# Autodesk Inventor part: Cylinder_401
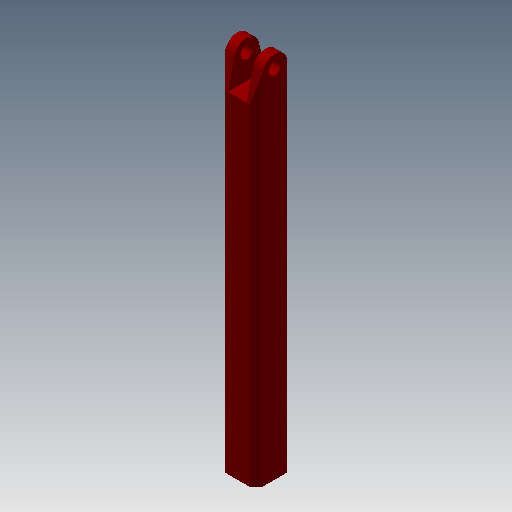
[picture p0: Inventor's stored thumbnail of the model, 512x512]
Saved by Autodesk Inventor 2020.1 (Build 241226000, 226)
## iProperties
Created: 2006-06
Part Number: Cylinder_401
Document SubType Name: Modeling
Designer: F.Stasiak
Density: 1 g/cm^3
Material: Ogólny
Appearance: Czerwony (matowy)
Manager: www.cadconsulting.pl
Company: Fabian Stasiak CAD Consulting
Author: F.Stasiak
Subject: Zbiór ćwiczeń. Autodesk Inventor 2020. Kurs podstawowy
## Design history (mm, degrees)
sketch "Szkic1"
  geometry: L1 (30, 0)-(-30, 0); L2 (-30, 0)-(-30, -530); L3 (-30, -530)-(30, -530); L4 (30, -530)-(30, 0); 2 further points
  constraints: 8 end point, 2 parallel, 1 coincident, 1 horizontal, 1 midpoint, 1 perpendicular
  dimensions: "d0" = 60 distance of L1.start L1.end; "d1" = 530 distance of L1.end L2.end
extrude "Wyciągnięcie proste1" new body sketch "Szkic1" stored distance "d2" = 60 (= d0); taper "d3" = 0 deg
sketch "Szkic2"
  geometry: L1 (-60, 530)-(0, 530) reference; L2 (-60, 530)-(-49.464, 574.598); L3 (-10.536, 574.598)-(0, 530); L4 (-30, 530)-(-30, 570); C1 r 10 at (-30, 570); A1 r 20 centre (-30, 570) between (-10.536, 574.598) and (-49.464, 574.598)
  constraints: 6 end point, 2 centre point, 2 point on circle, 2 tangent, 1 coincident, 1 midpoint, 1 vertical
  dimensions: "d4" = 40 distance of L4.start L4.end; "d5" = 20 radius of A1; "d6" = 20 diameter of C1
extrude "Wyciągnięcie proste2" join sketch "Szkic2" distance "d7" = 15; taper "d8" = 0 deg
node "Płaszczyzna konstrukcyjna1"
mirror "Lustro1"
chamfer "Faza1" distance "d9" = 10; stored, may be unused: second distance "d10" = 2, angle "d11" = 45 deg
sketch "Szkic3"
  geometry: L1 (-10, 10)-(-10, 50) reference; L2 (50, 10)-(50, 50) reference; L3 (-10, 30)-(50, 30); C1 r 17.5 at (20, 30)
  constraints: 3 midpoint, 2 end point, 1 centre point
  dimensions: "d12" = 35 diameter of C1
extrude "Wyciągnięcie proste3" cut sketch "Szkic3" distance "d13" = 480 (computed from d1); taper "d14" = 0 deg
node "Bryła1"
node "Korpusy bryłowe"
node "Korpusy powierzchniowe"
